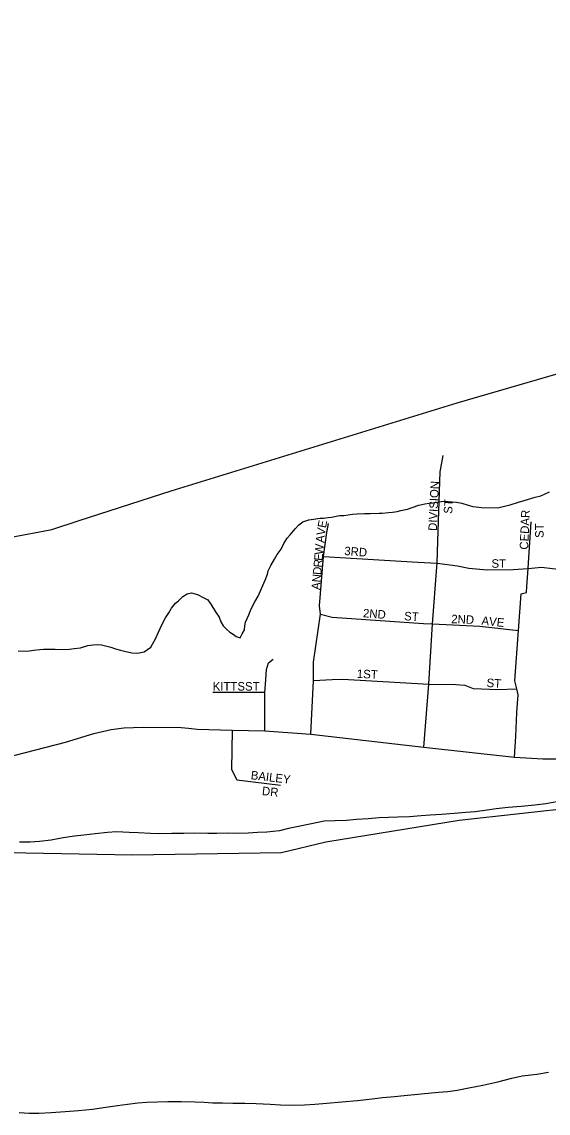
# Model space of a CAD drawing. Extents: x 1949938.81 to 1949945.61, y 152207.65 to 152214.09.
# Drawn here: x 1949942.704 to 1949943.289, y 152207.717 to 152208.931 of the extents above; entities that cross this region are included whole.
import ezdxf

# ---------------------------------------------------------------- set-up
doc = ezdxf.new("R2010")
doc.units = 0
for name, color, linetype in [('GM_X_County', 7, 'Continuous'), ('GM_X_County_Road', 7, 'Continuous'), ('GM_X_Major_River', 7, 'Continuous'), ('GM_X_Minor_River', 7, 'Continuous'), ('GM_X_Township', 7, 'Continuous'), ('GM_X_Township_ROW', 7, 'Continuous'), ('GM_X_Township_Subdivision', 7, 'Continuous'), ('GM_X_Township_Subdivision_Text', 7, 'Continuous'), ('GM_X_US_Route', 7, 'Continuous')]:
    doc.layers.add(name, color=color, linetype=linetype)

msp = doc.modelspace()

# ---------------------------------------------------------------- linework, layer by layer
at = {"layer": 'GM_X_County'}
msp.add_lwpolyline([(1949942.5103, 152208.0107), (1949942.8268, 152208.0046), (1949942.9926, 152208.0073), (1949943.0418, 152208.019), (1949943.1902, 152208.0433), (1949943.3242, 152208.0581), (1949943.5551, 152208.1009), (1949944.0013, 152208.2067), (1949944.0649, 152208.2317), (1949944.5237, 152208.3846), (1949944.9116, 152208.528), (1949945.0312, 152208.5697), (1949945.2633, 152208.6645), (1949945.3744, 152208.725), (1949945.418, 152208.7524), (1949945.4377, 152208.7581), (1949945.4771, 152208.7673), (1949945.504, 152208.7825), (1949945.5586, 152208.8115), (1949945.5958, 152208.8237), (1949945.6069, 152208.8266)], dxfattribs=at)
at = {"layer": 'GM_X_County_Road'}
msp.add_lwpolyline([(1949942.6732, 152208.1097), (1949942.7524, 152208.1298), (1949942.7839, 152208.1396), (1949942.8033, 152208.1441), (1949942.8174, 152208.1457), (1949942.8388, 152208.1466), (1949942.8811, 152208.1461), (1949942.8892, 152208.1454), (1949942.8989, 152208.1443), (1949942.9377, 152208.1434), (1949942.9742, 152208.1426), (1949943.0253, 152208.1388), (1949943.151, 152208.1245), (1949943.2515, 152208.1131), (1949943.2833, 152208.1115), (1949943.3015, 152208.1115)], dxfattribs=at)
at = {"layer": 'GM_X_Major_River'}
for points in [[(1949943.2987, 152208.0634), (1949943.2866, 152208.0615), (1949943.2741, 152208.06), (1949943.2589, 152208.0585), (1949943.2446, 152208.0574), (1949943.2313, 152208.0558), (1949943.2211, 152208.0543), (1949943.2079, 152208.0524), (1949943.1977, 152208.0517), (1949943.1844, 152208.0506), (1949943.1705, 152208.0494), (1949943.158, 152208.0487), (1949943.1478, 152208.0479), (1949943.1349, 152208.0468), (1949943.122, 152208.0464), (1949943.1012, 152208.0456), (1949943.0888, 152208.0445), (1949943.0759, 152208.0438), (1949943.0649, 152208.043), (1949943.0521, 152208.0426), (1949943.04, 152208.0419), (1949943.0241, 152208.0388), (1949943.0116, 152208.0362), (1949943.0003, 152208.0339), (1949942.9904, 152208.0313), (1949942.9761, 152208.0298), (1949942.9659, 152208.0294), (1949942.9553, 152208.0286), (1949942.9432, 152208.0282), (1949942.933, 152208.0286), (1949942.9205, 152208.0283), (1949942.9106, 152208.0283), (1949942.8959, 152208.0286), (1949942.8838, 152208.0283), (1949942.8706, 152208.0283), (1949942.8566, 152208.0279), (1949942.8467, 152208.0283), (1949942.8331, 152208.029), (1949942.8233, 152208.0294), (1949942.8089, 152208.0302), (1949942.7991, 152208.0294), (1949942.7855, 152208.0279), (1949942.7726, 152208.0264), (1949942.7624, 152208.0253), (1949942.7499, 152208.0237), (1949942.7363, 152208.0211), (1949942.7234, 152208.0196), (1949942.7132, 152208.0188), (1949942.7011, 152208.0188)], [(1949942.8327, 152207.7287), (1949942.8429, 152207.7294), (1949942.8663, 152207.7302), (1949942.8811, 152207.7302), (1949942.8966, 152207.7298), (1949942.9064, 152207.7294), (1949942.9162, 152207.729), (1949942.9268, 152207.7287), (1949942.9385, 152207.7286), (1949942.9518, 152207.7283), (1949942.9643, 152207.7279), (1949942.9801, 152207.7275), (1949942.9915, 152207.7267), (1949943.0055, 152207.7264), (1949943.018, 152207.7267), (1949943.0297, 152207.7275), (1949943.0429, 152207.7286), (1949943.0596, 152207.7298), (1949943.077, 152207.7316), (1949943.0932, 152207.7332), (1949943.1049, 152207.7347), (1949943.1182, 152207.7358), (1949943.1288, 152207.7369), (1949943.148, 152207.7388), (1949943.167, 152207.7407), (1949943.1775, 152207.7415), (1949943.1878, 152207.743), (1949943.201, 152207.7456), (1949943.2165, 152207.7483), (1949943.2331, 152207.7521), (1949943.2486, 152207.7562), (1949943.26, 152207.7589), (1949943.2763, 152207.7608), (1949943.2895, 152207.7631)], [(1949942.701, 152207.7181), (1949942.712, 152207.7173), (1949942.7226, 152207.7173), (1949942.7366, 152207.7181), (1949942.7521, 152207.7192), (1949942.7668, 152207.7203), (1949942.7824, 152207.7219), (1949942.7971, 152207.7241), (1949942.8103, 152207.726), (1949942.8213, 152207.7275), (1949942.8327, 152207.7287)]]:
    msp.add_lwpolyline(points, dxfattribs=at)
at = {"layer": 'GM_X_Minor_River'}
for points in [[(1949943.233, 152208.3907), (1949943.2421, 152208.3928), (1949943.247, 152208.3939), (1949943.2562, 152208.3968), (1949943.2623, 152208.3986), (1949943.2745, 152208.4025), (1949943.2809, 152208.4039), (1949943.2905, 152208.4083)], [(1949942.7408, 152208.2332), (1949942.754, 152208.233), (1949942.762, 152208.234), (1949942.7689, 152208.235), (1949942.7772, 152208.2375), (1949942.7833, 152208.2381), (1949942.7875, 152208.2385), (1949942.7924, 152208.238), (1949942.8026, 152208.2355), (1949942.8079, 152208.2339), (1949942.8135, 152208.2323), (1949942.818, 152208.2311), (1949942.8263, 152208.2294), (1949942.8324, 152208.229), (1949942.84, 152208.2304), (1949942.8473, 152208.2355), (1949942.8524, 152208.2449), (1949942.8559, 152208.2521), (1949942.8595, 152208.2604), (1949942.8634, 152208.2683), (1949942.8673, 152208.2739), (1949942.8704, 152208.2788), (1949942.8747, 152208.2844), (1949942.8781, 152208.287), (1949942.8827, 152208.2919), (1949942.8877, 152208.2948), (1949942.8923, 152208.2959), (1949942.8991, 152208.2943), (1949942.9062, 152208.2904), (1949942.9107, 152208.2884), (1949942.914, 152208.2834), (1949942.9192, 152208.2749), (1949942.9232, 152208.2688), (1949942.925, 152208.2638), (1949942.9276, 152208.2592), (1949942.9317, 152208.2554), (1949942.9351, 152208.2523), (1949942.9388, 152208.2499), (1949942.9422, 152208.2476), (1949942.9467, 152208.246), (1949942.9487, 152208.2505), (1949942.9514, 152208.2547), (1949942.9519, 152208.2592), (1949942.9527, 152208.2634), (1949942.9543, 152208.2675), (1949942.9562, 152208.2717), (1949942.959, 152208.2784), (1949942.9629, 152208.286), (1949942.9665, 152208.2924), (1949942.9704, 152208.3007), (1949942.9743, 152208.3101), (1949942.9771, 152208.3169), (1949942.9779, 152208.3206), (1949942.9807, 152208.3263), (1949942.9846, 152208.3334), (1949942.9877, 152208.3387), (1949942.992, 152208.3447), (1949942.9951, 152208.3507), (1949942.999, 152208.3567), (1949943.0021, 152208.3605), (1949943.0076, 152208.3672), (1949943.0118, 152208.3717), (1949943.0164, 152208.3751), (1949943.0229, 152208.3772), (1949943.0282, 152208.3779), (1949943.0354, 152208.3789), (1949943.0392, 152208.3792), (1949943.0445, 152208.3799), (1949943.0483, 152208.3802), (1949943.0571, 152208.382), (1949943.062, 152208.3822), (1949943.0715, 152208.3836), (1949943.0768, 152208.3839), (1949943.0847, 152208.3841), (1949943.0912, 152208.3844), (1949943.101, 152208.3846), (1949943.1044, 152208.3846), (1949943.1117, 152208.3852), (1949943.1158, 152208.3859), (1949943.1212, 152208.3866), (1949943.1253, 152208.3876), (1949943.1291, 152208.3883), (1949943.1326, 152208.389), (1949943.1379, 152208.3908), (1949943.1451, 152208.3934), (1949943.1486, 152208.3941), (1949943.152, 152208.3951), (1949943.1569, 152208.3958), (1949943.1607, 152208.3961), (1949943.1653, 152208.3968), (1949943.1702, 152208.3975), (1949943.174, 152208.3978), (1949943.1778, 152208.3977), (1949943.1819, 152208.3973), (1949943.1872, 152208.3968), (1949943.1929, 152208.3956), (1949943.2001, 152208.3936), (1949943.2053, 152208.392), (1949943.2091, 152208.3915), (1949943.2148, 152208.391), (1949943.233, 152208.3907)], [(1949942.6999, 152208.2316), (1949942.7074, 152208.2311), (1949942.7123, 152208.2314), (1949942.7169, 152208.2324), (1949942.7237, 152208.2331), (1949942.7279, 152208.2334), (1949942.7359, 152208.2333), (1949942.7408, 152208.2332)]]:
    msp.add_lwpolyline(points, dxfattribs=at)
at = {"layer": 'GM_X_Township'}
msp.add_lwpolyline([(1949942.5103, 152208.0107), (1949942.8268, 152208.0046), (1949942.9926, 152208.0073), (1949943.0418, 152208.019), (1949943.1902, 152208.0433), (1949943.3242, 152208.0581), (1949943.5551, 152208.1009), (1949944.0013, 152208.2067), (1949944.0649, 152208.2317), (1949944.5237, 152208.3846), (1949944.9116, 152208.528), (1949945.0312, 152208.5697), (1949945.2633, 152208.6645), (1949945.3744, 152208.725), (1949945.418, 152208.7524), (1949945.4377, 152208.7581), (1949945.4771, 152208.7673), (1949945.504, 152208.7825), (1949945.5586, 152208.8115), (1949945.5958, 152208.8237), (1949945.6069, 152208.8266)], dxfattribs=at)
at = {"layer": 'GM_X_Township_ROW'}
for points in [[(1949943.0253, 152208.1388), (1949943.0283, 152208.1986), (1949943.028, 152208.219), (1949943.0358, 152208.2722), (1949943.0348, 152208.2816)], [(1949942.9747, 152208.194), (1949942.9757, 152208.2106), (1949942.9781, 152208.218), (1949942.9831, 152208.2222)]]:
    msp.add_lwpolyline(points, dxfattribs=at)
at = {"layer": 'GM_X_Township_Subdivision'}
for points in [[(1949943.1664, 152208.3533), (1949943.1691, 152208.4304), (1949943.1722, 152208.4486)], [(1949943.0431, 152208.3631), (1949943.0447, 152208.3732)], [(1949943.2669, 152208.3235), (1949943.2702, 152208.3748)], [(1949943.0348, 152208.2816), (1949943.0348, 152208.2817), (1949943.0391, 152208.3366), (1949943.0431, 152208.3631)], [(1949943.1652, 152208.3247), (1949943.1655, 152208.3289), (1949943.1664, 152208.3533)], [(1949943.0391, 152208.3366), (1949943.1443, 152208.3303), (1949943.1655, 152208.3289), (1949943.1884, 152208.326), (1949943.2008, 152208.3233), (1949943.2213, 152208.3217), (1949943.2503, 152208.322), (1949943.2669, 152208.323), (1949943.2816, 152208.3246), (1949943.294, 152208.3232), (1949943.3289, 152208.3194)], [(1949943.151, 152208.1245), (1949943.1564, 152208.1943), (1949943.1606, 152208.2614), (1949943.1652, 152208.3247)], [(1949943.2654, 152208.303), (1949943.2669, 152208.323), (1949943.2669, 152208.3235)], [(1949943.2515, 152208.1131), (1949943.2531, 152208.1361), (1949943.2542, 152208.1628), (1949943.2558, 152208.1826), (1949943.2542, 152208.1891), (1949943.2519, 152208.1983), (1949943.256, 152208.254), (1949943.2591, 152208.2949), (1949943.2649, 152208.2964), (1949943.2654, 152208.303)], [(1949943.0358, 152208.2722), (1949943.0488, 152208.2691), (1949943.1506, 152208.262)], [(1949943.1506, 152208.262), (1949943.1606, 152208.2614), (1949943.2131, 152208.2589), (1949943.256, 152208.254)], [(1949943.0283, 152208.1986), (1949943.0489, 152208.1995)], [(1949943.0489, 152208.1995), (1949943.0609, 152208.2), (1949943.1564, 152208.1943), (1949943.1863, 152208.194), (1949943.1964, 152208.1932), (1949943.2056, 152208.1896), (1949943.233, 152208.1886), (1949943.2542, 152208.1891)], [(1949942.9161, 152208.1857), (1949942.9742, 152208.1857)], [(1949942.9742, 152208.1426), (1949942.9742, 152208.1857), (1949942.9747, 152208.194)], [(1949942.9377, 152208.1434), (1949942.9369, 152208.0997), (1949942.943, 152208.088), (1949942.9915, 152208.0822)]]:
    msp.add_lwpolyline(points, dxfattribs=at)
at = {"layer": 'GM_X_US_Route'}
for points in [[(1949942.7677, 152208.3764), (1949942.87, 152208.4095), (1949943.1879, 152208.5073), (1949943.3347, 152208.5501), (1949943.5527, 152208.6039), (1949943.6742, 152208.6353), (1949943.838, 152208.6715), (1949944.0262, 152208.7138), (1949944.1795, 152208.7497), (1949944.2642, 152208.7689), (1949944.2681, 152208.7698), (1949944.3644, 152208.7931), (1949944.4346, 152208.8128), (1949944.628, 152208.8938), (1949944.7057, 152208.9311)], [(1949942.3472, 152208.5215), (1949942.3663, 152208.5043), (1949942.4035, 152208.4709), (1949942.504, 152208.3868), (1949942.5534, 152208.373), (1949942.6225, 152208.3587), (1949942.6759, 152208.3548), (1949942.7371, 152208.3665), (1949942.7677, 152208.3764)]]:
    msp.add_lwpolyline(points, dxfattribs=at)

# ---------------------------------------------------------------- texts
at = {"layer": 'GM_X_Township_Subdivision_Text'}
for s, rotation, p in [('DIVISION', 87.2278, (1949943.1652, 152208.3647)), ('ST', 86.4256, (1949943.1823, 152208.3837)), ('CEDAR', 87.5647, (1949943.2668, 152208.3439)), ('V', 81.8639, (1949943.0407, 152208.3594)), ('E', 79.5325, (1949943.0419, 152208.3676)), ('ST', 90, (1949943.284, 152208.3571)), ('A', 84.8012, (1949943.04, 152208.3513)), ('W', 84.7878, (1949943.0387, 152208.338)), ('3RD', 355.6015, (1949943.0621, 152208.3381)), ('R', 84.7845, (1949943.0375, 152208.3239)), ('E', 84.7746, (1949943.0381, 152208.3313)), ('ST', 0, (1949943.2261, 152208.3239)), ('D', 84.7691, (1949943.0367, 152208.3156)), ('A', 84.7909, (1949943.0352, 152208.299)), ('N', 84.7765, (1949943.0359, 152208.3073)), ('2ND', 355.7635, (1949943.0829, 152208.2689)), ('ST', 356.4232, (1949943.1287, 152208.2656)), ('2ND', 357.8788, (1949943.1812, 152208.2623)), ('AVE', 354.0939, (1949943.2146, 152208.2606)), ('1ST', 357.5105, (1949943.0762, 152208.2014)), ('KITTS', 0, (1949942.9161, 152208.1873)), ('ST', 0, (1949942.952, 152208.1873)), ('ST', 356.1856, (1949943.2204, 152208.1914)), ('BAILEY', 353.2906, (1949942.958, 152208.0888)), ('DR', 353.9902, (1949942.9705, 152208.0712))]:
    msp.add_text(s, height=0.00947, rotation=rotation, dxfattribs=at).set_placement(p)

doc.saveas('drawing.dxf')
